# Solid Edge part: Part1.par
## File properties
Title: Index Feed
Author: Vicky Raina
Template: normal.par
Last saved by: Robert a Rhodes jr
Revision: 9
Application: Solid Edge
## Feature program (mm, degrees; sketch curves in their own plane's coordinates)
sketch for "unnamed Protrusion 1" plane through (0, 0, 0) normal (0, -1, 0) x-axis (1, 0, 0)
  line (-70.9604, 64.0839) -> (-70.9604, -73.7403)
  line (-70.9604, -73.7403) -> (54.0396, -73.7403)
  line (54.0396, -73.7403) -> (54.0396, -91.9161)
  line (54.0396, -91.9161) -> (129.0396, -91.9161)
  line (129.0396, -91.9161) -> (129.0396, -72.9161)
  line (129.0396, -72.9161) -> (254.0396, -72.9161)
  line (254.0396, -72.9161) -> (254.0396, 64.0839)
  line (254.0396, 64.0839) -> (-70.9604, 64.0839)
extrude "unnamed Protrusion 1" add finite 250 along -normal
sketch for "unnamed Cutout 1" plane through (-70.9604, 125, -4.8282) normal (-1, 0, 0) x-axis (0, -1, 0)
  line (-125, 14.6412) -> (-31, 68.9121)
  line (-30.1921, 85.7362) -> (-31, 68.9121)
  line (-156.4917, 85.7362) -> (-30.1921, 85.7362)
  line (-156.4917, 14.6412) -> (-156.4917, 85.7362)
  line (-125, 14.6412) -> (-156.4917, 14.6412)
  dimension (linear) = 125
extrude "unnamed Cutout 1" cut finite 290 along -normal
sketch for "unnamed Cutout 2" plane through (91.5396, 125, 64.0839) normal (0, 0, 1) x-axis (0, 1, 0)
  line (-125, 137.5) -> (86.3471, -37.5)
  line (-125, -194.3743) -> (-125, 137.5)
  line (125, -194.3743) -> (-125, -194.3743)
  line (125, -37.5) -> (125, -194.3743)
  line (125, -37.5) -> (87, -37.5)
extrude "unnamed Cutout 2" cut finite 62 along -normal
sketch for "unnamed Cutout 3" plane through (102.595, 125, 2.0839) normal (0, 0, 1) x-axis (0, 1, 0)
  line (-125, -51.4446) -> (-5.8246, -151.4446)
  line (-5.0536, -188.9251) -> (-5.8246, -151.4446)
  line (-164.4348, -188.9251) -> (-5.0536, -188.9251)
  line (-164.4348, -51.4446) -> (-164.4348, -188.9251)
  line (-125, -51.4446) -> (-164.4348, -51.4446)
extrude "unnamed Cutout 3" cut finite 19 along -normal
sketch for "unnamed Hole 1" plane through (102.595, 125, 2.0839) normal (0, 0, 1) x-axis (0, 1, 0)
  hole centre (-50, 10.5554) bore radius 25
hole "unnamed Hole 1" through
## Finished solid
Body 1: solid body, 19 faces, 46 edges, 28 vertices.
  Faces by surface: plane 17, cylinder 2
  Edges by curve: line 42, circle 4
Bounding box of the edges (mm): 325.000 x 250.000 x 156.000, from (-70.9604, 0, -91.9161) to (254.0396, 250, 64.0839).
Cylindrical faces by radius (mm): R25 x1, R37.5 x1
Planar faces by outward normal: +x 3, +y 1, +z 4, -x 2, -y 1, -z 3, oblique 3
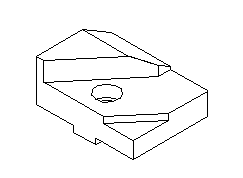
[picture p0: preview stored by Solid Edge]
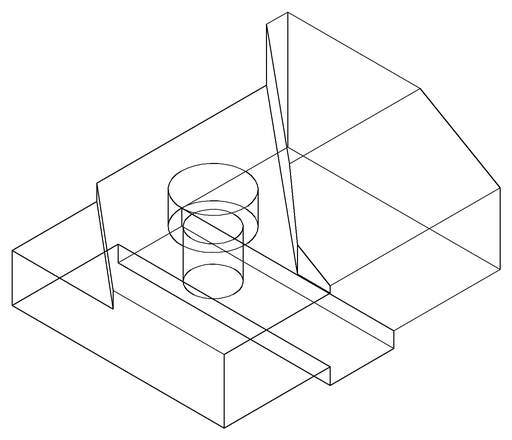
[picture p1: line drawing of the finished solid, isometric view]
